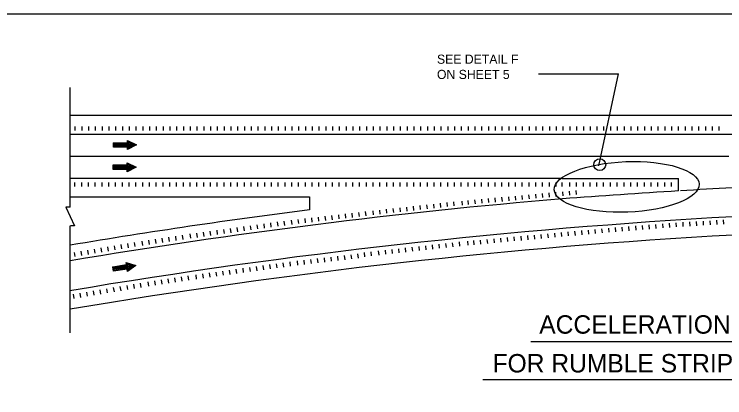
# Model space of a CAD drawing. Extents: x 632008 to 634206, y 294231 to 297795.
# Drawn here: x 632357 to 632590.2, y 295871.8 to 295997.6 of the extents above; entities that cross this region are included whole.
import ezdxf

# ---------------------------------------------------------------- set-up
doc = ezdxf.new("R2010")
doc.units = 0
doc.layers.add('1', color=7, linetype='Continuous')
doc.layers.add('2', color=7, linetype='Continuous')

msp = doc.modelspace()

# ---------------------------------------------------------------- linework, layer by layer
at = {"layer": '1'}
for p, q in [((632548.87, 295947.83), (632555.38, 295978.07)), ((632376.92, 295960.77), (632376.92, 295959.44)), ((632379.14, 295960.77), (632379.14, 295959.44)), ((632381.37, 295960.77), (632381.37, 295959.44)), ((632383.59, 295960.77), (632383.59, 295959.44)), ((632385.81, 295960.77), (632385.81, 295959.44)), ((632388.04, 295960.77), (632388.04, 295959.44)), ((632390.27, 295960.77), (632390.27, 295959.44)), ((632392.49, 295960.77), (632392.49, 295959.44)), ((632394.72, 295960.77), (632394.72, 295959.44)), ((632396.94, 295960.77), (632396.94, 295959.44)), ((632399.16, 295960.77), (632399.16, 295959.44)), ((632401.39, 295960.77), (632401.39, 295959.44)), ((632403.62, 295960.77), (632403.62, 295959.44)), ((632405.84, 295960.77), (632405.84, 295959.44)), ((632408.06, 295960.77), (632408.06, 295959.44)), ((632410.29, 295960.77), (632410.29, 295959.44)), ((632412.52, 295960.77), (632412.52, 295959.44)), ((632414.74, 295960.77), (632414.74, 295959.44)), ((632416.97, 295960.77), (632416.97, 295959.44)), ((632419.19, 295960.77), (632419.19, 295959.44)), ((632421.41, 295960.77), (632421.41, 295959.44)), ((632423.64, 295960.77), (632423.64, 295959.44)), ((632425.87, 295960.77), (632425.87, 295959.44)), ((632428.09, 295960.77), (632428.09, 295959.44)), ((632430.31, 295960.77), (632430.31, 295959.44)), ((632432.54, 295960.77), (632432.54, 295959.44)), ((632434.77, 295960.77), (632434.77, 295959.44)), ((632436.99, 295960.77), (632436.99, 295959.44)), ((632439.22, 295960.77), (632439.22, 295959.44)), ((632441.44, 295960.77), (632441.44, 295959.44)), ((632443.66, 295960.77), (632443.66, 295959.44)), ((632445.89, 295960.77), (632445.89, 295959.44)), ((632448.12, 295960.77), (632448.12, 295959.44)), ((632450.34, 295960.77), (632450.34, 295959.44)), ((632452.56, 295960.77), (632452.56, 295959.44)), ((632454.79, 295960.77), (632454.79, 295959.44)), ((632457.01, 295960.77), (632457.01, 295959.44)), ((632459.24, 295960.77), (632459.24, 295959.44)), ((632461.47, 295960.77), (632461.47, 295959.44)), ((632463.69, 295960.77), (632463.69, 295959.44)), ((632465.91, 295960.77), (632465.91, 295959.44)), ((632468.14, 295960.77), (632468.14, 295959.44)), ((632470.36, 295960.77), (632470.36, 295959.44)), ((632472.59, 295960.77), (632472.59, 295959.44)), ((632474.81, 295960.77), (632474.81, 295959.44)), ((632477.04, 295960.77), (632477.04, 295959.44)), ((632479.26, 295960.77), (632479.26, 295959.44)), ((632481.49, 295960.77), (632481.49, 295959.44)), ((632483.72, 295960.77), (632483.72, 295959.44)), ((632485.94, 295960.77), (632485.94, 295959.44)), ((632488.16, 295960.77), (632488.16, 295959.44)), ((632490.39, 295960.77), (632490.39, 295959.44)), ((632492.61, 295960.77), (632492.61, 295959.44)), ((632494.84, 295960.77), (632494.84, 295959.44)), ((632497.06, 295960.77), (632497.06, 295959.44)), ((632499.29, 295960.77), (632499.29, 295959.44)), ((632501.51, 295960.77), (632501.51, 295959.44)), ((632503.74, 295960.77), (632503.74, 295959.44)), ((632505.96, 295960.77), (632505.96, 295959.44)), ((632508.19, 295960.77), (632508.19, 295959.44)), ((632510.41, 295960.77), (632510.41, 295959.44)), ((632512.64, 295960.77), (632512.64, 295959.44)), ((632514.86, 295960.77), (632514.86, 295959.44)), ((632517.09, 295960.77), (632517.09, 295959.44)), ((632519.31, 295960.77), (632519.31, 295959.44)), ((632521.54, 295960.77), (632521.54, 295959.44)), ((632523.76, 295960.77), (632523.76, 295959.44)), ((632525.99, 295960.77), (632525.99, 295959.44)), ((632528.21, 295960.77), (632528.21, 295959.44)), ((632530.44, 295960.77), (632530.44, 295959.44)), ((632532.66, 295960.77), (632532.66, 295959.44)), ((632534.89, 295960.77), (632534.89, 295959.44)), ((632537.11, 295960.77), (632537.11, 295959.44)), ((632539.34, 295960.77), (632539.34, 295959.44)), ((632541.56, 295960.77), (632541.56, 295959.44)), ((632543.79, 295960.77), (632543.79, 295959.44)), ((632546.01, 295960.77), (632546.01, 295959.44)), ((632548.24, 295960.77), (632548.24, 295959.44)), ((632550.46, 295960.77), (632550.46, 295959.44)), ((632552.69, 295960.77), (632552.69, 295959.44)), ((632554.91, 295960.77), (632554.91, 295959.44)), ((632557.14, 295960.77), (632557.14, 295959.44)), ((632559.36, 295960.77), (632559.36, 295959.44)), ((632561.59, 295960.77), (632561.59, 295959.44)), ((632563.81, 295960.77), (632563.81, 295959.44)), ((632566.04, 295960.77), (632566.04, 295959.44)), ((632568.26, 295960.77), (632568.26, 295959.44)), ((632570.49, 295960.77), (632570.49, 295959.44)), ((632572.71, 295960.77), (632572.71, 295959.44)), ((632574.94, 295960.77), (632574.94, 295959.44)), ((632577.16, 295960.77), (632577.16, 295959.44)), ((632579.39, 295960.77), (632579.39, 295959.44)), ((632581.61, 295960.77), (632581.61, 295959.44)), ((632583.84, 295960.77), (632583.84, 295959.44)), ((632586.06, 295960.77), (632586.06, 295959.44)), ((632588.29, 295960.77), (632588.29, 295959.44)), ((632376.92, 295941.09), (632376.92, 295942.42)), ((632379.14, 295941.09), (632379.14, 295942.42)), ((632381.37, 295941.09), (632381.37, 295942.42)), ((632383.59, 295941.09), (632383.59, 295942.42)), ((632385.81, 295941.09), (632385.81, 295942.42)), ((632388.04, 295941.09), (632388.04, 295942.42)), ((632390.27, 295941.09), (632390.27, 295942.42)), ((632392.49, 295941.09), (632392.49, 295942.42)), ((632394.72, 295941.09), (632394.72, 295942.42)), ((632396.94, 295941.09), (632396.94, 295942.42)), ((632399.16, 295941.09), (632399.16, 295942.42)), ((632401.39, 295941.09), (632401.39, 295942.42)), ((632403.62, 295941.09), (632403.62, 295942.42)), ((632405.84, 295941.09), (632405.84, 295942.42)), ((632408.06, 295941.09), (632408.06, 295942.42)), ((632410.29, 295941.09), (632410.29, 295942.42)), ((632412.52, 295941.09), (632412.52, 295942.42)), ((632414.74, 295941.09), (632414.74, 295942.42)), ((632416.97, 295941.09), (632416.97, 295942.42)), ((632419.19, 295941.09), (632419.19, 295942.42)), ((632421.41, 295941.09), (632421.41, 295942.42)), ((632423.64, 295941.09), (632423.64, 295942.42)), ((632425.87, 295941.09), (632425.87, 295942.42)), ((632428.09, 295941.09), (632428.09, 295942.42)), ((632430.31, 295941.09), (632430.31, 295942.42)), ((632432.54, 295941.09), (632432.54, 295942.42)), ((632434.77, 295941.09), (632434.77, 295942.42)), ((632436.99, 295941.09), (632436.99, 295942.42)), ((632439.22, 295941.09), (632439.22, 295942.42)), ((632441.44, 295941.09), (632441.44, 295942.42)), ((632443.66, 295941.09), (632443.66, 295942.42)), ((632445.89, 295941.09), (632445.89, 295942.42)), ((632448.12, 295941.09), (632448.12, 295942.42)), ((632450.34, 295941.09), (632450.34, 295942.42)), ((632452.56, 295941.09), (632452.56, 295942.42)), ((632454.79, 295941.09), (632454.79, 295942.42)), ((632457.01, 295941.09), (632457.01, 295942.42)), ((632459.24, 295941.09), (632459.24, 295942.42)), ((632461.47, 295941.09), (632461.47, 295942.42)), ((632463.69, 295941.09), (632463.69, 295942.42)), ((632465.91, 295941.09), (632465.91, 295942.42)), ((632468.14, 295941.09), (632468.14, 295942.42)), ((632470.36, 295941.09), (632470.36, 295942.42)), ((632472.59, 295941.09), (632472.59, 295942.42)), ((632474.81, 295941.09), (632474.81, 295942.42)), ((632477.04, 295941.09), (632477.04, 295942.42)), ((632479.26, 295941.09), (632479.26, 295942.42)), ((632481.49, 295941.09), (632481.49, 295942.42)), ((632483.72, 295941.09), (632483.72, 295942.42)), ((632485.94, 295941.09), (632485.94, 295942.42)), ((632488.16, 295941.09), (632488.16, 295942.42)), ((632490.39, 295941.09), (632490.39, 295942.42)), ((632492.61, 295941.09), (632492.61, 295942.42)), ((632494.84, 295941.09), (632494.84, 295942.42)), ((632497.06, 295941.09), (632497.06, 295942.42)), ((632499.29, 295941.09), (632499.29, 295942.42)), ((632501.51, 295941.09), (632501.51, 295942.42)), ((632503.74, 295941.09), (632503.74, 295942.42)), ((632505.96, 295941.09), (632505.96, 295942.42)), ((632508.19, 295941.09), (632508.19, 295942.42)), ((632510.41, 295941.09), (632510.41, 295942.42)), ((632512.64, 295941.09), (632512.64, 295942.42)), ((632514.86, 295941.09), (632514.86, 295942.42)), ((632517.09, 295941.09), (632517.09, 295942.42)), ((632519.31, 295941.09), (632519.31, 295942.42)), ((632521.54, 295941.09), (632521.54, 295942.42)), ((632523.76, 295941.09), (632523.76, 295942.42)), ((632525.99, 295941.09), (632525.99, 295942.42)), ((632528.21, 295941.09), (632528.21, 295942.42)), ((632530.44, 295941.09), (632530.44, 295942.42)), ((632532.66, 295941.09), (632532.66, 295942.42)), ((632534.89, 295941.09), (632534.89, 295942.42)), ((632536.87, 295941.09), (632536.87, 295942.42)), ((632539.34, 295941.09), (632539.34, 295942.42)), ((632541.56, 295941.09), (632541.56, 295942.42)), ((632543.79, 295941.09), (632543.79, 295942.42)), ((632546.01, 295941.09), (632546.01, 295942.42)), ((632548.24, 295941.09), (632548.24, 295942.42)), ((632550.46, 295941.09), (632550.46, 295942.42)), ((632552.69, 295941.09), (632552.69, 295942.42)), ((632554.91, 295941.09), (632554.91, 295942.42)), ((632557.14, 295941.09), (632557.14, 295942.42)), ((632559.36, 295941.09), (632559.36, 295942.42)), ((632561.59, 295941.09), (632561.59, 295942.42)), ((632563.81, 295941.09), (632563.81, 295942.42)), ((632566.04, 295941.09), (632566.04, 295942.42)), ((632568.26, 295941.09), (632568.26, 295942.42)), ((632570.49, 295941.09), (632570.49, 295942.42)), ((632572.71, 295941.09), (632572.71, 295942.42)), ((632575, 295939.64), (632575, 295943.73)), ((632539.35, 295938.26), (632539.23, 295939.6)), ((632541.56, 295938.47), (632541.44, 295939.8)), ((632515, 295936.01), (632514.87, 295937.34)), ((632517.21, 295936.21), (632517.09, 295937.55)), ((632519.43, 295936.42), (632519.3, 295937.75)), ((632521.64, 295936.62), (632521.52, 295937.96)), ((632523.85, 295936.83), (632523.73, 295938.16)), ((632526.07, 295937.03), (632525.94, 295938.37)), ((632528.28, 295937.24), (632528.16, 295938.57)), ((632530.5, 295937.44), (632530.37, 295938.78)), ((632532.71, 295937.65), (632532.59, 295938.98)), ((632534.92, 295937.85), (632534.8, 295939.19)), ((632537.14, 295938.06), (632537.01, 295939.39)), ((632492.6, 295933.77), (632492.46, 295935.1)), ((632494.81, 295934.01), (632494.67, 295935.34)), ((632497.02, 295934.26), (632496.88, 295935.59)), ((632499.23, 295934.51), (632499.09, 295935.83)), ((632501.44, 295934.75), (632501.3, 295936.08)), ((632504.17, 295935), (632504.05, 295936.34)), ((632506.14, 295935.18), (632506.02, 295936.52)), ((632508.36, 295935.39), (632508.23, 295936.73)), ((632510.57, 295935.6), (632510.45, 295936.93)), ((632512.78, 295935.8), (632512.66, 295937.14)), ((632470.28, 295931.24), (632470.11, 295932.62)), ((632472.48, 295931.5), (632472.32, 295932.88)), ((632474.92, 295931.81), (632474.78, 295933.14)), ((632477.13, 295932.06), (632476.99, 295933.38)), ((632479.34, 295932.3), (632479.2, 295933.63)), ((632481.55, 295932.55), (632481.41, 295933.87)), ((632483.76, 295932.79), (632483.62, 295934.12)), ((632485.97, 295933.04), (632485.83, 295934.36)), ((632488.18, 295933.28), (632488.04, 295934.61)), ((632490.39, 295933.53), (632490.25, 295934.85)), ((632450.4, 295928.93), (632450.24, 295930.31)), ((632452.61, 295929.19), (632452.45, 295930.57)), ((632454.82, 295929.44), (632454.66, 295930.82)), ((632457.02, 295929.7), (632456.86, 295931.08)), ((632459.23, 295929.96), (632459.07, 295931.34)), ((632461.44, 295930.21), (632461.28, 295931.6)), ((632463.65, 295930.47), (632463.49, 295931.85)), ((632465.86, 295930.73), (632465.7, 295932.11)), ((632468.07, 295930.98), (632467.91, 295932.37)), ((632432.57, 295926.55), (632432.38, 295927.95)), ((632434.77, 295926.86), (632434.58, 295928.25)), ((632436.97, 295927.16), (632436.78, 295928.55)), ((632439.18, 295927.46), (632438.98, 295928.86)), ((632441.38, 295927.77), (632441.19, 295929.16)), ((632443.58, 295928.07), (632443.39, 295929.47)), ((632445.79, 295928.34), (632445.59, 295929.77)), ((632448.19, 295928.67), (632448.03, 295930.05)), ((632558.87, 295926.61), (632558.76, 295927.97)), ((632561.09, 295926.79), (632560.98, 295928.15)), ((632563.31, 295926.96), (632563.2, 295928.32)), ((632565.52, 295927.14), (632565.41, 295928.5)), ((632567.74, 295927.31), (632567.63, 295928.67)), ((632569.95, 295927.49), (632569.85, 295928.85)), ((632572.17, 295927.66), (632572.06, 295929.02)), ((632574.39, 295927.83), (632574.31, 295929.22)), ((632576.61, 295927.96), (632576.53, 295929.35)), ((632578.83, 295928.1), (632578.75, 295929.49)), ((632581.05, 295928.23), (632580.97, 295929.62)), ((632583.27, 295928.37), (632583.18, 295929.76)), ((632585.49, 295928.51), (632585.4, 295929.89)), ((632587.71, 295928.64), (632587.62, 295930.03)), ((632589.93, 295928.78), (632589.84, 295930.16)), ((632417.15, 295924.42), (632416.96, 295925.82)), ((632419.35, 295924.73), (632419.16, 295926.12)), ((632421.56, 295925.03), (632421.36, 295926.43)), ((632423.76, 295925.34), (632423.57, 295926.73)), ((632425.96, 295925.64), (632425.77, 295927.04)), ((632428.16, 295925.94), (632427.97, 295927.34)), ((632430.37, 295926.25), (632430.17, 295927.64)), ((632532.31, 295924.26), (632532.19, 295925.6)), ((632534.53, 295924.47), (632534.4, 295925.8)), ((632536.74, 295924.67), (632536.62, 295926.01)), ((632538.96, 295924.88), (632538.83, 295926.21)), ((632541.17, 295925.08), (632541.05, 295926.42)), ((632543.38, 295925.29), (632543.26, 295926.62)), ((632545.6, 295925.49), (632545.47, 295926.83)), ((632547.81, 295925.7), (632547.69, 295927.03)), ((632550.03, 295925.9), (632549.9, 295927.24)), ((632552.22, 295926.08), (632552.12, 295927.44)), ((632554.44, 295926.26), (632554.33, 295927.62)), ((632556.66, 295926.44), (632556.55, 295927.79)), ((632401.41, 295922.09), (632401.19, 295923.49)), ((632403.6, 295922.43), (632403.39, 295923.83)), ((632405.8, 295922.76), (632405.59, 295924.16)), ((632408, 295923.09), (632407.79, 295924.49)), ((632410.2, 295923.43), (632409.99, 295924.82)), ((632412.4, 295923.76), (632412.19, 295925.16)), ((632414.95, 295924.12), (632414.76, 295925.52)), ((632507.96, 295922.01), (632507.84, 295923.34)), ((632510.17, 295922.21), (632510.05, 295923.55)), ((632512.39, 295922.42), (632512.26, 295923.75)), ((632514.6, 295922.62), (632514.48, 295923.96)), ((632516.82, 295922.83), (632516.69, 295924.16)), ((632519.03, 295923.03), (632518.91, 295924.37)), ((632521.24, 295923.24), (632521.12, 295924.57)), ((632523.46, 295923.44), (632523.33, 295924.78)), ((632525.67, 295923.65), (632525.55, 295924.98)), ((632527.89, 295923.85), (632527.76, 295925.19)), ((632530.1, 295924.06), (632529.98, 295925.39)), ((632385.74, 295919.56), (632385.51, 295920.96)), ((632387.94, 295919.92), (632387.71, 295921.32)), ((632390.13, 295920.29), (632389.9, 295921.69)), ((632392.32, 295920.65), (632392.09, 295922.05)), ((632394.52, 295921.02), (632394.29, 295922.42)), ((632396.71, 295921.38), (632396.48, 295922.78)), ((632399.21, 295921.76), (632399, 295923.16)), ((632485.58, 295919.61), (632485.44, 295920.94)), ((632487.79, 295919.86), (632487.64, 295921.19)), ((632490, 295920.1), (632489.85, 295921.43)), ((632492.21, 295920.35), (632492.06, 295921.67)), ((632494.42, 295920.59), (632494.27, 295921.92)), ((632496.63, 295920.84), (632496.48, 295922.16)), ((632498.84, 295921.08), (632498.69, 295922.41)), ((632501.05, 295921.33), (632500.9, 295922.65)), ((632503.26, 295921.57), (632503.11, 295922.9)), ((632505.99, 295921.82), (632505.86, 295923.16)), ((632376.97, 295918.1), (632376.74, 295919.5)), ((632379.16, 295918.47), (632378.93, 295919.87)), ((632381.36, 295918.83), (632381.13, 295920.23)), ((632383.55, 295919.2), (632383.32, 295920.59)), ((632467.78, 295917.35), (632467.62, 295918.73)), ((632469.98, 295917.61), (632469.82, 295918.99)), ((632472.09, 295918.06), (632471.93, 295919.44)), ((632474.3, 295918.32), (632474.14, 295919.7)), ((632476.74, 295918.63), (632476.6, 295919.96)), ((632478.95, 295918.88), (632478.81, 295920.21)), ((632481.16, 295919.12), (632481.02, 295920.45)), ((632483.37, 295919.37), (632483.22, 295920.69)), ((632447.67, 295915.01), (632447.51, 295916.39)), ((632450.11, 295915.29), (632449.95, 295916.68)), ((632452.32, 295915.55), (632452.16, 295916.93)), ((632454.53, 295915.81), (632454.36, 295917.19)), ((632456.73, 295916.06), (632456.57, 295917.45)), ((632458.94, 295916.32), (632458.78, 295917.7)), ((632461.15, 295916.58), (632460.99, 295917.96)), ((632463.36, 295916.84), (632463.2, 295918.22)), ((632465.57, 295917.09), (632465.41, 295918.47)), ((632430.08, 295912.56), (632429.89, 295913.96)), ((632432.28, 295912.87), (632432.09, 295914.26)), ((632434.49, 295913.17), (632434.29, 295914.57)), ((632436.69, 295913.48), (632436.5, 295914.87)), ((632438.89, 295913.78), (632438.7, 295915.18)), ((632441.09, 295914.08), (632440.9, 295915.48)), ((632443.3, 295914.39), (632443.1, 295915.78)), ((632445.5, 295914.69), (632445.31, 295916.09)), ((632414.32, 295910.38), (632414.1, 295911.78)), ((632416.87, 295910.74), (632416.67, 295912.14)), ((632419.07, 295911.05), (632418.88, 295912.44)), ((632421.27, 295911.35), (632421.08, 295912.75)), ((632423.47, 295911.65), (632423.28, 295913.05)), ((632425.68, 295911.96), (632425.48, 295913.35)), ((632427.88, 295912.26), (632427.69, 295913.66)), ((632398.63, 295908), (632398.4, 295909.4)), ((632401.13, 295908.38), (632400.91, 295909.78)), ((632403.32, 295908.71), (632403.11, 295910.11)), ((632405.52, 295909.05), (632405.31, 295910.45)), ((632407.72, 295909.38), (632407.51, 295910.78)), ((632409.92, 295909.71), (632409.71, 295911.11)), ((632412.12, 295910.05), (632411.91, 295911.45)), ((632385.47, 295905.82), (632385.24, 295907.22)), ((632387.66, 295906.18), (632387.43, 295907.58)), ((632389.86, 295906.55), (632389.62, 295907.95)), ((632392.05, 295906.91), (632391.82, 295908.31)), ((632394.24, 295907.27), (632394.01, 295908.67)), ((632396.44, 295907.64), (632396.2, 295909.04)), ((632376.7, 295904.36), (632376.46, 295905.76)), ((632378.89, 295904.72), (632378.66, 295906.12)), ((632381.08, 295905.09), (632380.85, 295906.49)), ((632383.28, 295905.45), (632383.04, 295906.85))]:
    msp.add_line(p, q, dxfattribs=at)
msp.add_lwpolyline([(632833.86, 295433.62), (632833.86, 295997.62), (632047.86, 295997.62), (632047.86, 295433.62), (632833.86, 295433.62), (632833.86, 295459.98), (632633.86, 295459.98), (632633.86, 295524.66), (632833.86, 295524.66), (632833.86, 295553.62), (632633.86, 295553.62), (632633.86, 295433.62), (632712.66, 295433.62), (632712.66, 295459.98), (632712.66, 295433.62), (632789.66, 295433.62), (632789.66, 295459.98), (632789.66, 295447.66), (632833.86, 295447.66)], dxfattribs=at)
msp.add_lwpolyline([(632833.86, 295433.62), (632833.86, 295997.62), (632047.86, 295997.62), (632047.86, 295433.62), (632833.86, 295433.62), (632833.86, 295459.98), (632633.86, 295459.98), (632633.86, 295524.66), (632833.86, 295524.66), (632833.86, 295553.62), (632633.86, 295553.62), (632633.86, 295433.62), (632712.66, 295433.62), (632712.66, 295459.98), (632712.66, 295433.62), (632789.66, 295433.62), (632789.66, 295459.98), (632789.66, 295447.66), (632833.86, 295447.66)], dxfattribs=at)
msp.add_lwpolyline([(632833.86, 295433.62), (632833.86, 295997.62), (632047.86, 295997.62), (632047.86, 295433.62), (632833.86, 295433.62), (632833.86, 295459.98), (632633.86, 295459.98), (632633.86, 295524.66), (632833.86, 295524.66), (632833.86, 295553.62), (632633.86, 295553.62), (632633.86, 295433.62), (632712.66, 295433.62), (632712.66, 295459.98), (632712.66, 295433.62), (632789.66, 295433.62), (632789.66, 295459.98), (632789.66, 295447.66), (632833.86, 295447.66)], dxfattribs=at)
msp.add_lwpolyline([(632833.86, 295433.62), (632833.86, 295997.62), (632047.86, 295997.62), (632047.86, 295433.62), (632833.86, 295433.62), (632833.86, 295459.98), (632633.86, 295459.98), (632633.86, 295524.66), (632833.86, 295524.66), (632833.86, 295553.62), (632633.86, 295553.62), (632633.86, 295433.62), (632712.66, 295433.62), (632712.66, 295459.98), (632712.66, 295433.62), (632789.66, 295433.62), (632789.66, 295459.98), (632789.66, 295447.66), (632833.86, 295447.66)], dxfattribs=at)
msp.add_circle((632549.18, 295948.26), 1.94, dxfattribs=at)
msp.add_ellipse((632558.02, 295940.97), major_axis=(23.78, 0.92), ratio=0.348493, dxfattribs=at)
at = {"layer": '2'}
for p, q in [((632529.11, 295978.07), (632555.38, 295978.07)), ((632375.3, 295934.32), (632375.3, 295973.59)), ((632375.3, 295964.48), (632592.68, 295964.48)), ((632592.68, 295958.13), (632375.3, 295958.13)), ((632591.57, 295950.93), (632375.3, 295950.93)), ((632536.87, 295943.73), (632375.3, 295943.73)), ((632536.87, 295943.73), (632575, 295943.73)), ((632375.3, 295937.73), (632453.95, 295937.73)), ((632453.95, 295937.73), (632453.95, 295933.43)), ((632373.97, 295934.32), (632376.78, 295928.22)), ((632375.3, 295934.32), (632373.97, 295934.32)), ((632375.3, 295893.08), (632375.3, 295928.22)), ((632376.78, 295928.22), (632375.46, 295928.22)), ((632526.57, 295890.29), (632673.28, 295890.29)), ((632510.77, 295877.77), (632688.38, 295877.77))]:
    msp.add_line(p, q, dxfattribs=at)
for points in [[(632389.63, 295955.47), (632394.13, 295955.47), (632394.13, 295956.22), (632397.13, 295954.72), (632394.13, 295953.22), (632394.13, 295953.97), (632389.63, 295953.97), (632389.63, 295955.47)], [(632389.78, 295955.32), (632394.28, 295955.32), (632394.28, 295955.92), (632396.68, 295954.72), (632394.28, 295953.52), (632394.28, 295954.12), (632389.78, 295954.12), (632389.78, 295955.17), (632394.58, 295955.17), (632394.43, 295955.62), (632396.08, 295954.72), (632394.43, 295953.82), (632394.58, 295954.42), (632390.08, 295954.42), (632390.08, 295955.02), (632394.88, 295955.02), (632395.48, 295954.72), (632394.88, 295954.42), (632394.88, 295954.72), (632390.23, 295954.72)], [(632389.78, 295955.32), (632389.63, 295955.47)], [(632389.51, 295948.16), (632394.01, 295948.16), (632394.01, 295948.91), (632397.01, 295947.41), (632394.01, 295945.91), (632394.01, 295946.66), (632389.51, 295946.66), (632389.51, 295948.16)], [(632389.66, 295948.01), (632389.51, 295948.16)], [(632389.66, 295948.01), (632394.16, 295948.01), (632394.16, 295948.61), (632396.56, 295947.41), (632394.16, 295946.21), (632394.16, 295946.81), (632389.66, 295946.81), (632389.66, 295947.86), (632394.46, 295947.86), (632394.31, 295948.31), (632395.96, 295947.41), (632394.31, 295946.51), (632394.46, 295947.11), (632389.96, 295947.11), (632389.96, 295947.71), (632394.76, 295947.71), (632395.36, 295947.41), (632394.76, 295947.11), (632394.76, 295947.41), (632390.11, 295947.41)], [(632389.37, 295914.8), (632393.82, 295915.48), (632393.7, 295916.22), (632396.9, 295915.19), (632394.16, 295913.26), (632394.04, 295914), (632389.59, 295913.32), (632389.37, 295914.8)], [(632389.54, 295914.67), (632389.37, 295914.8)], [(632389.54, 295914.67), (632393.98, 295915.36), (632393.9, 295915.95), (632396.45, 295915.13), (632394.26, 295913.58), (632394.17, 295914.17), (632389.72, 295913.49), (632389.56, 295914.53), (632394.31, 295915.25), (632394.09, 295915.68), (632395.86, 295915.03), (632394.36, 295913.9), (632394.42, 295914.51), (632389.97, 295913.83), (632389.88, 295914.43), (632394.62, 295915.15), (632395.26, 295914.94), (632394.71, 295914.56), (632394.67, 295914.85), (632390.07, 295914.15)]]:
    msp.add_lwpolyline(points, dxfattribs=at)
for centre, radius, start, end in [((632774.98, 292702.64), 3243.17, 93.53522, 94.20929), ((632774.98, 292702.64), 3243.17, 93.22216, 93.52385), ((632700.23, 293988.78), 1955.11, 94.79117, 99.56504), ((632699.95, 293993.86), 1955.11, 97.22836, 99.55527), ((632700.4, 293979.01), 1955.11, 93.15336, 99.57394), ((632700.4, 293979.01), 1949.11, 93.15999, 99.59978)]:
    msp.add_arc(centre, radius, start, end, dxfattribs=at)

# ---------------------------------------------------------------- texts
at = {"layer": '1'}
for s, height, p in [('SEE DETAIL F', 3, (632495.75, 295981.37)), ('ON SHEET 5', 3, (632495.75, 295976.37)), ('ACCELERATION LANE DETAIL', 6.0395, (632529.32, 295892.82)), ('FOR RUMBLE STRIP INSTALLATION', 6.0395, (632513.99, 295880.1))]:
    msp.add_text(s, height=height, dxfattribs=at).set_placement(p)

doc.saveas('drawing.dxf')
